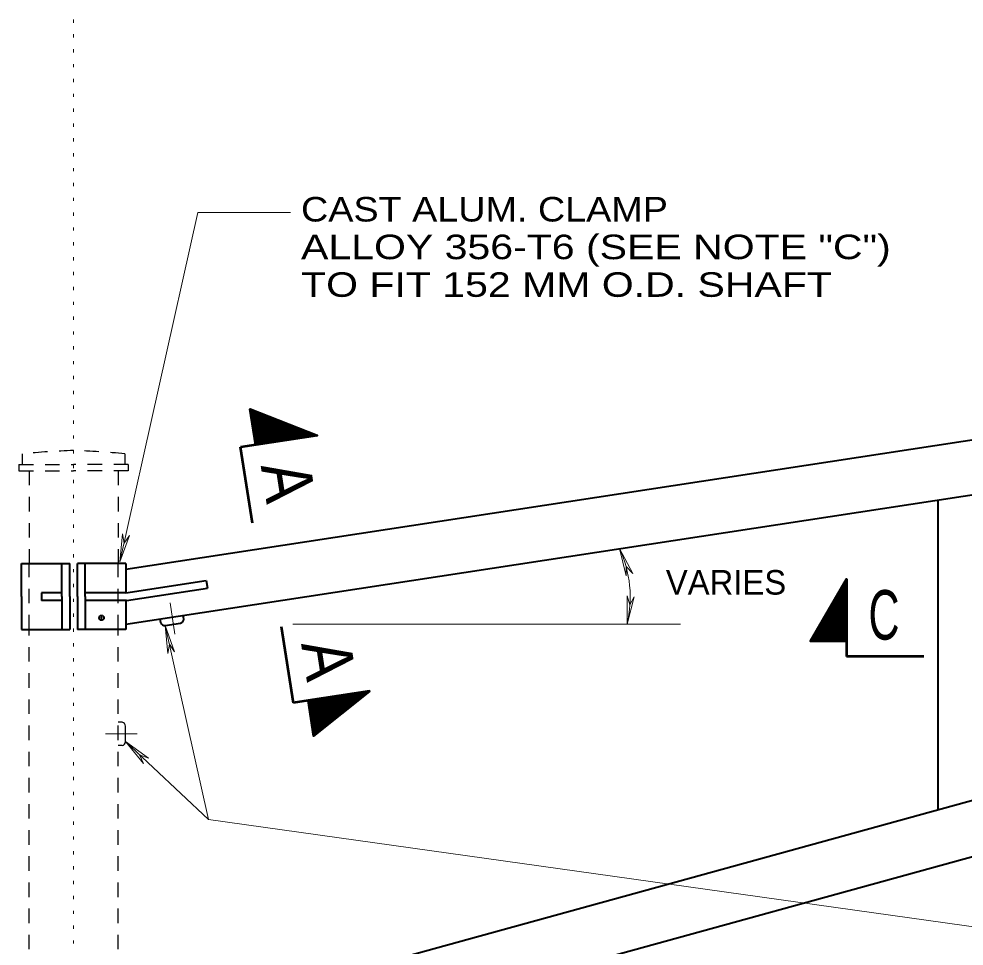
# Model space of a CAD drawing. Extents: x 312583 to 312854, y 144419 to 144597.
# Drawn here: x 312726.54 to 312755.82, y 144539.43 to 144568.14 of the extents above; entities that cross this region are included whole.
import ezdxf
from ezdxf.enums import TextEntityAlignment as Align

# ---------------------------------------------------------------- set-up
doc = ezdxf.new("R2010")
doc.units = 0
doc.header["$LTSCALE"] = 0.3
doc.header["$PDMODE"] = 32
doc.header["$PDSIZE"] = 0.15
doc.linetypes.add('DOTTED', pattern=[1.5, 0.3, -1.2])
doc.linetypes.add('SHORT_DASHED', pattern=[2.7, 1.5, -1.2])
doc.layers.add('1', color=7, linetype='Continuous', lineweight=40)

msp = doc.modelspace()

# ---------------------------------------------------------------- linework, layer by layer
at = {"layer": '1', "linetype": 'DOTTED', "lineweight": 13}
msp.add_line((312728.2319, 144528.9275), (312728.2319, 144573.4478), dxfattribs=at)
at = {"layer": '1'}
for p, q in [((312729.8495, 144551.1072), (312833.1655, 144566.9005)), ((312729.8495, 144549.4052), (312833.4185, 144565.2368)), ((312729.8495, 144536.7322), (312829.0255, 144564.0332)), ((312729.8649, 144534.9918), (312829.4702, 144562.4155)), ((312755.0039, 144553.2538), (312755.0039, 144543.6552)), ((312726.6142, 144551.2758), (312728.1169, 144551.2758)), ((312726.6142, 144550.2562), (312726.6142, 144551.2758)), ((312727.8715, 144550.2562), (312727.8715, 144551.2758)), ((312728.1169, 144550.2562), (312728.1169, 144551.2758)), ((312729.8495, 144551.2758), (312728.3545, 144551.2758)), ((312728.3545, 144550.2562), (312728.3545, 144551.2758)), ((312728.5922, 144550.2562), (312728.5922, 144551.2758)), ((312729.8495, 144551.2758), (312729.8495, 144550.3712)), ((312729.8495, 144550.3712), (312732.3412, 144550.7545)), ((312732.3412, 144550.7545), (312732.3795, 144550.5168)), ((312729.8725, 144550.1335), (312732.3795, 144550.5168)), ((312726.6142, 144550.2562), (312726.6142, 144549.2365)), ((312727.2352, 144550.3712), (312727.2352, 144550.1335)), ((312727.8715, 144550.3712), (312727.2352, 144550.3712)), ((312727.8715, 144550.2562), (312727.8715, 144549.2365)), ((312728.1169, 144550.2562), (312728.1169, 144549.2365)), ((312728.3545, 144550.2562), (312728.3545, 144549.2365)), ((312729.8495, 144550.3712), (312728.5922, 144550.3712)), ((312728.5922, 144550.2562), (312728.5922, 144549.2365)), ((312727.8715, 144550.1335), (312727.2352, 144550.1335)), ((312729.8725, 144550.1335), (312728.5922, 144550.1335)), ((312729.8495, 144550.1335), (312729.8495, 144549.2365)), ((312730.9382, 144549.4435), (312730.9152, 144549.5738)), ((312731.6435, 144549.5508), (312731.6282, 144549.6812)), ((312731.0685, 144549.3592), (312731.5439, 144549.4358))]:
    msp.add_line(p, q, dxfattribs=at)
at = {"layer": '1', "lineweight": 13}
for p, q in [((312729.6655, 144551.3295), (312732.0805, 144562.1472)), ((312732.0805, 144562.1472), (312734.9555, 144562.1472)), ((312729.6655, 144551.3295), (312729.7499, 144552.1958)), ((312729.7499, 144552.1958), (312729.7959, 144551.9045)), ((312729.6655, 144551.3295), (312729.9645, 144552.1498)), ((312729.9645, 144552.1498), (312729.7959, 144551.9045)), ((312745.1445, 144551.7435), (312745.3515, 144550.9002)), ((312745.1445, 144551.7435), (312745.5509, 144550.9692)), ((312745.3515, 144550.9002), (312745.3515, 144551.1915)), ((312745.5509, 144550.9692), (312745.3515, 144551.1915)), ((312745.3822, 144550.2792), (312745.4589, 144549.9955)), ((312745.3822, 144549.4052), (312745.3822, 144550.2792)), ((312745.3822, 144549.4052), (312745.5969, 144550.2485)), ((312745.5969, 144550.2485), (312745.4589, 144549.9955)), ((312731.2219, 144550.0645), (312731.3675, 144549.0908)), ((312732.4102, 144543.3562), (312731.0685, 144549.3592)), ((312731.0685, 144549.3592), (312731.1529, 144548.4928)), ((312731.0685, 144549.3592), (312731.3599, 144548.5388)), ((312735.0245, 144549.4052), (312747.0305, 144549.4052)), ((312731.1529, 144548.4928), (312731.1989, 144548.7842)), ((312731.3599, 144548.5388), (312731.1989, 144548.7842)), ((312729.2209, 144546.0088), (312730.2022, 144546.0088)), ((312729.8419, 144545.7635), (312730.4015, 144545.0888)), ((312729.8419, 144545.7635), (312730.5472, 144545.2498)), ((312730.4015, 144545.0888), (312730.2712, 144545.3572)), ((312730.5472, 144545.2498), (312730.2712, 144545.3572))]:
    msp.add_line(p, q, dxfattribs=at)
at = {"layer": '1', "lineweight": 35}
for p, q in [((312733.7135, 144556.0292), (312733.7289, 144556.0445)), ((312733.7212, 144555.9832), (312733.7519, 144556.0368)), ((312733.7289, 144555.9295), (312733.7672, 144556.0292)), ((312733.7365, 144555.8835), (312733.7902, 144556.0138)), ((312733.7442, 144555.8298), (312733.8209, 144556.0138)), ((312733.7519, 144555.7915), (312733.8362, 144555.9985)), ((312733.7595, 144555.7378), (312733.8592, 144555.9908)), ((312733.7672, 144555.6918), (312733.8822, 144555.9832)), ((312733.7749, 144555.6458), (312733.8975, 144555.9755)), ((312733.7825, 144555.5998), (312733.9359, 144555.9678)), ((312733.7902, 144555.5462), (312733.9512, 144555.9602)), ((312733.7979, 144555.5002), (312733.9742, 144555.9525)), ((312733.7979, 144555.4618), (312733.9972, 144555.9448)), ((312733.8132, 144555.4082), (312734.0125, 144555.9372)), ((312733.8132, 144555.3622), (312734.0355, 144555.9295)), ((312733.8209, 144555.3162), (312734.0585, 144555.9142)), ((312733.8285, 144555.2625), (312734.0815, 144555.9065)), ((312733.8362, 144555.2165), (312734.1045, 144555.8988)), ((312733.8439, 144555.1705), (312734.1199, 144555.8912)), ((312733.8515, 144555.1245), (312734.1505, 144555.8758)), ((312733.8592, 144555.0708), (312734.1735, 144555.8758)), ((312733.8669, 144555.0325), (312734.1889, 144555.8605)), ((312733.8745, 144554.9788), (312734.2195, 144555.8528)), ((312733.8899, 144554.9635), (312734.2349, 144555.8452)), ((312733.9205, 144554.9635), (312734.2655, 144555.8375)), ((312733.9512, 144554.9712), (312734.2885, 144555.8298)), ((312733.9742, 144554.9712), (312734.3039, 144555.8222)), ((312734.0049, 144554.9788), (312734.3269, 144555.8145)), ((312734.0279, 144554.9865), (312734.3499, 144555.8068)), ((312734.0585, 144554.9942), (312734.3729, 144555.7915)), ((312734.0815, 144554.9865), (312734.3959, 144555.7915)), ((312734.1122, 144554.9942), (312734.4189, 144555.7762)), ((312734.1429, 144555.0018), (312734.4342, 144555.7685)), ((312734.1659, 144555.0018), (312734.4572, 144555.7608)), ((312734.1965, 144555.0095), (312734.4879, 144555.7532)), ((312734.2272, 144555.0095), (312734.5109, 144555.7378)), ((312734.2502, 144555.0172), (312734.5262, 144555.7302)), ((312734.2809, 144555.0248), (312734.5492, 144555.7225)), ((312734.3115, 144555.0248), (312734.5722, 144555.7148)), ((312734.3345, 144555.0248), (312734.5952, 144555.7072)), ((312734.3575, 144555.0325), (312734.6182, 144555.6995)), ((312734.3882, 144555.0402), (312734.6412, 144555.6918)), ((312734.4189, 144555.0402), (312734.6565, 144555.6842)), ((312734.4495, 144555.0478), (312734.6872, 144555.6688)), ((312734.4725, 144555.0478), (312734.7102, 144555.6688)), ((312734.5032, 144555.0555), (312734.7255, 144555.6535)), ((312734.5185, 144555.0632), (312734.7562, 144555.6535)), ((312734.5492, 144555.0632), (312734.7715, 144555.6382)), ((312734.5722, 144555.0632), (312734.8022, 144555.6305)), ((312734.6029, 144555.0708), (312734.8252, 144555.6228)), ((312734.6335, 144555.0785), (312734.8405, 144555.6075)), ((312734.6565, 144555.0785), (312734.8635, 144555.6075)), ((312734.6872, 144555.0862), (312734.8865, 144555.5922)), ((312734.7179, 144555.0862), (312734.9095, 144555.5922)), ((312734.7409, 144555.0938), (312734.9325, 144555.5768)), ((312734.7715, 144555.0938), (312734.9555, 144555.5768)), ((312734.8022, 144555.1015), (312734.9709, 144555.5615)), ((312734.8252, 144555.1015), (312734.9939, 144555.5538)), ((312734.8482, 144555.1092), (312735.0245, 144555.5462)), ((312734.8789, 144555.1092), (312735.0475, 144555.5385)), ((312734.9095, 144555.1168), (312735.0629, 144555.5308)), ((312734.9402, 144555.1245), (312735.0859, 144555.5155)), ((312734.9632, 144555.1245), (312735.1089, 144555.5155)), ((312734.9939, 144555.1322), (312735.1319, 144555.5002)), ((312735.0169, 144555.1322), (312735.1549, 144555.4848)), ((312735.0475, 144555.1398), (312735.1779, 144555.4848)), ((312735.0705, 144555.1398), (312735.1932, 144555.4695)), ((312735.1012, 144555.1475), (312735.2162, 144555.4695)), ((312735.1319, 144555.1475), (312735.2469, 144555.4542)), ((312735.1549, 144555.1552), (312735.2622, 144555.4465)), ((312735.1779, 144555.1552), (312735.2929, 144555.4388)), ((312735.2009, 144555.1628), (312735.3082, 144555.4312)), ((312735.2315, 144555.1705), (312735.3312, 144555.4235)), ((312735.2622, 144555.1705), (312735.3619, 144555.4158)), ((312735.2852, 144555.1782), (312735.3772, 144555.4082)), ((312735.3159, 144555.1782), (312735.4002, 144555.4005)), ((312735.3389, 144555.1858), (312735.4232, 144555.3928)), ((312735.3695, 144555.1858), (312735.4462, 144555.3775)), ((312735.4002, 144555.1935), (312735.4692, 144555.3698)), ((312735.4309, 144555.1935), (312735.4922, 144555.3622)), ((312735.4539, 144555.2012), (312735.5075, 144555.3468)), ((312735.4845, 144555.2088), (312735.5305, 144555.3468)), ((312735.5075, 144555.2088), (312735.5612, 144555.3315)), ((312735.5305, 144555.2088), (312735.5842, 144555.3315)), ((312735.5612, 144555.2165), (312735.5995, 144555.3162)), ((312735.5919, 144555.2242), (312735.6225, 144555.3085)), ((312735.6225, 144555.2242), (312735.6455, 144555.3008)), ((312735.6455, 144555.2318), (312735.6685, 144555.2932)), ((312735.6762, 144555.2318), (312735.6915, 144555.2855)), ((312735.6992, 144555.2395), (312735.7145, 144555.2778)), ((312735.7299, 144555.2395), (312735.7299, 144555.2702)), ((312735.7605, 144555.2472), (312735.7529, 144555.2625)), ((312752.1749, 144550.7162), (312752.1365, 144550.7392)), ((312752.1749, 144550.7468), (312752.1519, 144550.7545)), ((312752.1749, 144550.7775), (312752.1595, 144550.7775)), ((312752.1749, 144550.3328), (312751.9679, 144550.4478)), ((312752.1749, 144550.3558), (312751.9832, 144550.4708)), ((312752.1749, 144550.3865), (312751.9985, 144550.4862)), ((312752.1749, 144550.4172), (312752.0062, 144550.5092)), ((312752.1749, 144550.4478), (312752.0215, 144550.5322)), ((312752.1749, 144550.4708), (312752.0369, 144550.5475)), ((312752.1749, 144550.5015), (312752.0445, 144550.5705)), ((312752.1749, 144550.5245), (312752.0599, 144550.5935)), ((312752.1749, 144550.5475), (312752.0675, 144550.6165)), ((312752.1749, 144550.5782), (312752.0829, 144550.6318)), ((312752.1749, 144550.6088), (312752.0905, 144550.6548)), ((312752.1749, 144550.6395), (312752.1059, 144550.6778)), ((312752.1749, 144550.6625), (312752.1135, 144550.6932)), ((312752.1749, 144550.6932), (312752.1289, 144550.7162)), ((312752.1749, 144549.9495), (312751.8069, 144550.1565)), ((312752.1749, 144549.9725), (312751.8145, 144550.1795)), ((312752.1749, 144550.0032), (312751.8299, 144550.1948)), ((312752.1749, 144550.0262), (312751.8452, 144550.2178)), ((312752.1749, 144550.0568), (312751.8529, 144550.2408)), ((312752.1749, 144550.0798), (312751.8682, 144550.2562)), ((312752.1749, 144550.1105), (312751.8759, 144550.2792)), ((312752.1749, 144550.1412), (312751.8912, 144550.3022)), ((312752.1749, 144550.1642), (312751.8989, 144550.3175)), ((312752.1749, 144550.1948), (312751.9142, 144550.3482)), ((312752.1749, 144550.2178), (312751.9219, 144550.3635)), ((312752.1749, 144550.2485), (312751.9372, 144550.3865)), ((312752.1749, 144550.2792), (312751.9449, 144550.4095)), ((312752.1749, 144550.3022), (312751.9602, 144550.4248)), ((312752.1672, 144549.5278), (312751.6229, 144549.8498)), ((312752.1749, 144549.5585), (312751.6382, 144549.8652)), ((312752.1749, 144549.5815), (312751.6535, 144549.8882)), ((312752.1749, 144549.6122), (312751.6612, 144549.9112)), ((312752.1749, 144549.6428), (312751.6765, 144549.9265)), ((312752.1749, 144549.6658), (312751.6842, 144549.9495)), ((312752.1749, 144549.6965), (312751.6995, 144549.9725)), ((312752.1749, 144549.7272), (312751.7072, 144549.9878)), ((312752.1749, 144549.7502), (312751.7225, 144550.0108)), ((312752.1749, 144549.7808), (312751.7302, 144550.0338)), ((312752.1749, 144549.8115), (312751.7455, 144550.0492)), ((312752.1749, 144549.8345), (312751.7532, 144550.0722)), ((312752.1749, 144549.8575), (312751.7685, 144550.0952)), ((312752.1749, 144549.8882), (312751.7762, 144550.1182)), ((312752.1749, 144549.9188), (312751.7915, 144550.1335)), ((312752.1749, 144549.1675), (312751.4695, 144549.5738)), ((312752.1749, 144549.1982), (312751.4849, 144549.5968)), ((312752.1749, 144549.2288), (312751.5002, 144549.6198)), ((312752.1749, 144549.2518), (312751.5079, 144549.6352)), ((312752.1672, 144549.2825), (312751.5232, 144549.6582)), ((312752.1749, 144549.3132), (312751.5309, 144549.6812)), ((312752.1749, 144549.3362), (312751.5462, 144549.6965)), ((312752.1749, 144549.3592), (312751.5539, 144549.7195)), ((312752.1749, 144549.3898), (312751.5692, 144549.7425)), ((312752.1749, 144549.4205), (312751.5769, 144549.7578)), ((312752.1749, 144549.4512), (312751.5922, 144549.7808)), ((312752.1749, 144549.4742), (312751.5999, 144549.8038)), ((312752.1749, 144549.5048), (312751.6152, 144549.8192)), ((312752.0062, 144548.8762), (312751.3085, 144549.2825)), ((312752.0599, 144548.8762), (312751.3162, 144549.3055)), ((312752.0982, 144548.8762), (312751.3315, 144549.3208)), ((312752.1519, 144548.8762), (312751.3392, 144549.3515)), ((312752.1749, 144548.8915), (312751.3545, 144549.3668)), ((312752.1749, 144548.9222), (312751.3622, 144549.3898)), ((312752.1749, 144548.9528), (312751.3775, 144549.4128)), ((312752.1749, 144548.9758), (312751.3852, 144549.4282)), ((312752.1749, 144549.0065), (312751.4005, 144549.4512)), ((312752.1672, 144549.0295), (312751.4082, 144549.4742)), ((312752.1672, 144549.0602), (312751.4235, 144549.4895)), ((312752.1749, 144549.0832), (312751.4312, 144549.5125)), ((312752.1749, 144549.1138), (312751.4465, 144549.5355)), ((312752.1749, 144549.1445), (312751.4619, 144549.5508)), ((312751.2932, 144548.8762), (312751.1245, 144548.9758)), ((312751.3315, 144548.8762), (312751.1399, 144548.9912)), ((312751.3852, 144548.8762), (312751.1475, 144549.0142)), ((312751.4312, 144548.8762), (312751.1629, 144549.0372)), ((312751.4772, 144548.8762), (312751.1705, 144549.0525)), ((312751.5232, 144548.8762), (312751.1859, 144549.0832)), ((312751.5769, 144548.8762), (312751.1935, 144549.0985)), ((312751.6229, 144548.8762), (312751.2089, 144549.1215)), ((312751.6689, 144548.8762), (312751.2165, 144549.1445)), ((312751.7225, 144548.8762), (312751.2319, 144549.1598)), ((312751.7685, 144548.8762), (312751.2395, 144549.1828)), ((312751.8145, 144548.8762), (312751.2549, 144549.1982)), ((312751.8682, 144548.8762), (312751.2702, 144549.2212)), ((312751.9142, 144548.8762), (312751.2779, 144549.2442)), ((312751.9602, 144548.8762), (312751.2932, 144549.2595)), ((312751.0939, 144548.8762), (312751.0785, 144548.8915)), ((312751.1399, 144548.8762), (312751.0862, 144548.9145)), ((312751.1935, 144548.8762), (312751.1015, 144548.9298)), ((312751.2395, 144548.8762), (312751.1169, 144548.9528)), ((312736.6652, 144547.2202), (312736.8952, 144546.9288)), ((312736.6882, 144547.2202), (312736.9105, 144546.9442)), ((312736.7189, 144547.2278), (312736.9335, 144546.9518)), ((312736.7495, 144547.2278), (312736.9489, 144546.9748)), ((312736.7725, 144547.2355), (312736.9642, 144546.9825)), ((312736.8032, 144547.2355), (312736.9949, 144547.0055)), ((312736.8262, 144547.2432), (312737.0102, 144547.0132)), ((312736.8569, 144547.2432), (312737.0255, 144547.0285)), ((312736.8875, 144547.2508), (312737.0485, 144547.0438)), ((312736.9105, 144547.2508), (312737.0639, 144547.0592)), ((312736.9412, 144547.2585), (312737.0869, 144547.0745)), ((312736.9642, 144547.2585), (312737.1022, 144547.0898)), ((312736.9949, 144547.2662), (312737.1175, 144547.1052)), ((312737.0255, 144547.2738), (312737.1405, 144547.1205)), ((312737.0562, 144547.2738), (312737.1635, 144547.1358)), ((312737.0792, 144547.2815), (312737.1712, 144547.1512)), ((312737.1099, 144547.2815), (312737.1942, 144547.1665)), ((312737.1252, 144547.2892), (312737.2172, 144547.1818)), ((312737.1482, 144547.2892), (312737.2325, 144547.1972)), ((312737.1789, 144547.2968), (312737.2479, 144547.2125)), ((312737.2095, 144547.2968), (312737.2709, 144547.2202)), ((312737.2402, 144547.3045), (312737.2939, 144547.2432)), ((312737.2632, 144547.3122), (312737.3015, 144547.2508)), ((312737.2939, 144547.3122), (312737.3245, 144547.2738)), ((312737.3169, 144547.3198), (312737.3475, 144547.2815)), ((312737.3475, 144547.3198), (312737.3629, 144547.2968)), ((312737.3782, 144547.3275), (312737.3782, 144547.3122)), ((312735.4999, 144547.0132), (312736.0979, 144546.2848)), ((312735.5152, 144547.0362), (312736.1132, 144546.3002)), ((312735.5152, 144546.9595), (312736.0672, 144546.2695)), ((312735.5459, 144547.0438), (312736.1285, 144546.3155)), ((312735.5765, 144547.0515), (312736.1515, 144546.3308)), ((312735.5995, 144547.0515), (312736.1669, 144546.3385)), ((312735.6302, 144547.0592), (312736.1822, 144546.3615)), ((312735.6532, 144547.0515), (312736.2052, 144546.3692)), ((312735.6839, 144547.0592), (312736.2205, 144546.3845)), ((312735.7069, 144547.0668), (312736.2435, 144546.3998)), ((312735.7375, 144547.0745), (312736.2589, 144546.4152)), ((312735.7682, 144547.0745), (312736.2742, 144546.4382)), ((312735.7912, 144547.0822), (312736.2972, 144546.4458)), ((312735.8219, 144547.0822), (312736.3202, 144546.4612)), ((312735.8449, 144547.0898), (312736.3355, 144546.4842)), ((312735.8679, 144547.0975), (312736.3509, 144546.4918)), ((312735.9062, 144547.0898), (312736.3739, 144546.5148)), ((312735.9292, 144547.1052), (312736.3969, 144546.5225)), ((312735.9522, 144547.1052), (312736.4045, 144546.5378)), ((312735.9752, 144547.1128), (312736.4275, 144546.5532)), ((312736.0059, 144547.1128), (312736.4505, 144546.5685)), ((312736.0365, 144547.1205), (312736.4659, 144546.5762)), ((312736.0672, 144547.1205), (312736.4812, 144546.5992)), ((312736.0902, 144547.1282), (312736.5042, 144546.6068)), ((312736.1209, 144547.1358), (312736.5195, 144546.6298)), ((312736.1439, 144547.1282), (312736.5425, 144546.6375)), ((312736.1745, 144547.1435), (312736.5579, 144546.6605)), ((312736.1975, 144547.1435), (312736.5809, 144546.6758)), ((312736.2282, 144547.1512), (312736.6039, 144546.6835)), ((312736.2589, 144547.1512), (312736.6115, 144546.7065)), ((312736.2819, 144547.1588), (312736.6345, 144546.7142)), ((312736.3125, 144547.1588), (312736.6575, 144546.7372)), ((312736.3432, 144547.1665), (312736.6729, 144546.7448)), ((312736.3662, 144547.1665), (312736.6882, 144546.7602)), ((312736.3969, 144547.1742), (312736.7112, 144546.7755)), ((312736.4275, 144547.1818), (312736.7265, 144546.7908)), ((312736.4505, 144547.1818), (312736.7495, 144546.7985)), ((312736.4735, 144547.1895), (312736.7649, 144546.8215)), ((312736.4965, 144547.1895), (312736.7879, 144546.8292)), ((312736.5272, 144547.1972), (312736.8032, 144546.8522)), ((312736.5579, 144547.1972), (312736.8185, 144546.8675)), ((312736.5809, 144547.2048), (312736.8415, 144546.8752)), ((312736.6115, 144547.2048), (312736.8569, 144546.8982)), ((312736.6345, 144547.2125), (312736.8722, 144546.9135)), ((312735.5152, 144546.9212), (312736.0519, 144546.2542)), ((312735.5229, 144546.8675), (312736.0365, 144546.2388)), ((312735.5305, 144546.8215), (312736.0135, 144546.2235)), ((312735.5382, 144546.7755), (312735.9982, 144546.2082)), ((312735.5459, 144546.7372), (312735.9752, 144546.1928)), ((312735.5535, 144546.6835), (312735.9599, 144546.1775)), ((312735.5612, 144546.6375), (312735.9445, 144546.1622)), ((312735.5689, 144546.5915), (312735.9215, 144546.1468)), ((312735.5765, 144546.5378), (312735.9139, 144546.1315)), ((312735.5842, 144546.4918), (312735.8909, 144546.1162)), ((312735.5919, 144546.4458), (312735.8679, 144546.1008)), ((312735.5995, 144546.3922), (312735.8525, 144546.0932)), ((312735.6072, 144546.3462), (312735.8295, 144546.0702)), ((312735.6149, 144546.3002), (312735.8142, 144546.0625)), ((312735.6225, 144546.2542), (312735.7912, 144546.0395)), ((312735.6302, 144546.2005), (312735.7682, 144546.0318)), ((312735.6302, 144546.1622), (312735.7605, 144546.0165)), ((312735.6455, 144546.1162), (312735.7375, 144546.0012)), ((312735.6455, 144546.0702), (312735.7145, 144545.9858)), ((312735.6609, 144546.0165), (312735.7069, 144545.9705)), ((312735.6609, 144545.9705), (312735.6839, 144545.9552))]:
    msp.add_line(p, q, dxfattribs=at)
at = {"layer": '1', "lineweight": 53}
for p, q in [((312733.8745, 144554.9558), (312733.4069, 144554.8868)), ((312733.7749, 144552.5255), (312733.4069, 144554.8868)), ((312734.6642, 144549.3285), (312735.0322, 144546.9672)), ((312752.1749, 144548.8762), (312752.1749, 144548.4008)), ((312754.5669, 144548.4008), (312752.1749, 144548.4008)), ((312735.4999, 144547.0362), (312735.0322, 144546.9672))]:
    msp.add_line(p, q, dxfattribs=at)
at = {"layer": '1', "linetype": 'SHORT_DASHED', "lineweight": 25}
for p, q in [((312726.6449, 144554.3425), (312726.6449, 144554.6798)), ((312729.8265, 144554.3425), (312729.8265, 144554.6798)), ((312726.5375, 144554.3425), (312728.2319, 144554.3425)), ((312726.5375, 144554.3425), (312726.5375, 144554.1508)), ((312729.9262, 144554.3425), (312728.2319, 144554.3425)), ((312729.9262, 144554.3425), (312729.9262, 144554.1508)), ((312726.5375, 144554.1508), (312728.2319, 144554.1508)), ((312726.8595, 144554.1508), (312726.8595, 144551.2758)), ((312729.9262, 144554.1508), (312728.2319, 144554.1508)), ((312729.6119, 144554.1508), (312729.6119, 144551.2758)), ((312726.8595, 144549.2365), (312726.8595, 144551.2758)), ((312729.6119, 144549.2365), (312729.6119, 144551.2758)), ((312726.8595, 144536.9008), (312726.8595, 144549.2365)), ((312729.6119, 144536.9008), (312729.6119, 144549.2365))]:
    msp.add_line(p, q, dxfattribs=at)
at = {"layer": '1', "lineweight": 25}
for p, q in [((312729.7345, 144546.3615), (312729.6119, 144546.3615)), ((312729.8419, 144545.7635), (312729.8419, 144546.2388)), ((312729.7345, 144545.6408), (312729.6119, 144545.6408))]:
    msp.add_line(p, q, dxfattribs=at)
at = {"layer": '1', "lineweight": 53}
for points in [[(312733.8745, 144554.9558), (312733.7059, 144556.0598), (312735.7759, 144555.2472)], [(312752.1749, 144548.8762), (312751.0632, 144548.8762), (312752.1749, 144550.7928)], [(312735.4999, 144547.0362), (312735.6685, 144545.9398), (312737.3935, 144547.3275)]]:
    msp.add_lwpolyline(points, close=True, dxfattribs=at)
at = {"layer": '1'}
for points in [[(312726.6142, 144549.2365), (312727.8715, 144549.2365), (312728.1169, 144549.2365)], [(312729.8495, 144549.2365), (312728.5922, 144549.2365), (312728.3545, 144549.2365)]]:
    msp.add_lwpolyline(points, dxfattribs=at)
at = {"layer": '1', "lineweight": 13}
msp.add_lwpolyline([(312758.6915, 144539.6685), (312732.4102, 144543.3562), (312729.8419, 144545.7635)], dxfattribs=at)
at = {"layer": '1', "linetype": 'SHORT_DASHED', "lineweight": 25}
for centre, start, end in [((312729.0538, 144529.9468), 91.89125, 95.56371), ((312727.4138, 144529.9468), 84.43629, 88.10875)]:
    msp.add_arc(centre, 24.8462, start, end, dxfattribs=at)
at = {"layer": '1', "lineweight": 13}
msp.add_arc((312741.8841, 144550.241), 3.5904, 346.57037, 24.76396, dxfattribs=at)
at = {"layer": '1'}
for centre, start, end in [((312731.0503, 144549.4781), 195.83064, 278.98563), ((312731.525, 144549.551), 278.4852, 1.56735)]:
    msp.add_arc(centre, 0.1193, start, end, dxfattribs=at)
at = {"layer": '1', "lineweight": 25}
for centre, start, end in [((312729.7219, 144546.2425), 359.7352, 82.81735), ((312729.7217, 144545.7623), 277.08064, 0.23563)]:
    msp.add_arc(centre, 0.1193, start, end, dxfattribs=at)
at = {"layer": '1'}
msp.add_point((312729.0982, 144549.5968), dxfattribs=at)

# ---------------------------------------------------------------- texts
for s, width, p in [('CAST ALUM. CLAMP', 1.15, (312735.2775, 144561.8702)), ('ALLOY 356-T6 (SEE NOTE "C")', 1.25, (312735.2775, 144560.7039)), ('TO FIT 152 MM O.D. SHAFT', 1.25, (312735.2775, 144559.5376))]:
    msp.add_text(s, height=0.76, dxfattribs=dict(at, width=width)).set_placement(p)
at = {"layer": '1', "width": 0.9}
for p in [(312734.1212, 144553.6987), (312735.3708, 144548.1863)]:
    msp.add_text('A', height=1.533, rotation=278.758, dxfattribs=at).set_placement(p, align=Align.CENTER)
at = {"layer": '1'}
msp.add_text('VARIES', height=0.76, dxfattribs=at).set_placement((312746.5783, 144550.3166))
at = {"layer": '1', "width": 0.65}
msp.add_text('C', height=1.533, dxfattribs=at).set_placement((312753.3364, 144548.9222), align=Align.CENTER)

doc.saveas('drawing.dxf')
